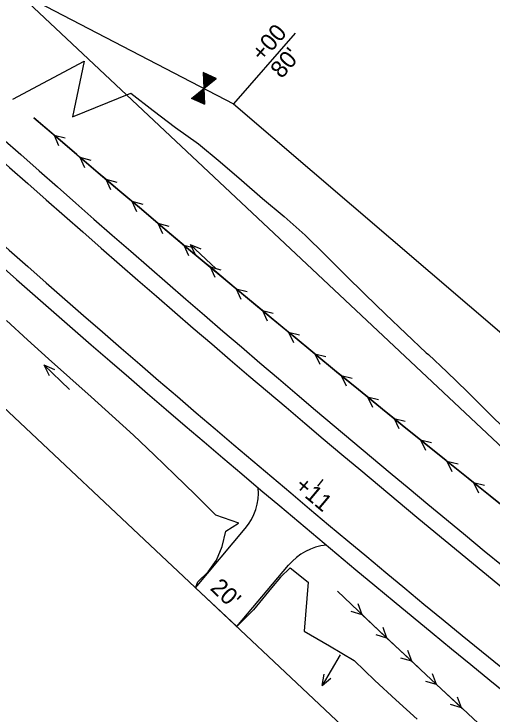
# Model space of a CAD drawing. Extents: x 1006695 to 1009377, y 1883329 to 1886115.
# Drawn here: x 1007248.3 to 1007416.8, y 1885056.9 to 1885303.6 of the extents above; entities that cross this region are included whole.
import ezdxf

# ---------------------------------------------------------------- set-up
doc = ezdxf.new("R2010")
doc.units = 0
for name, color, linetype in [('R_Drainage Ditch Lining', 7, 'Continuous'), ('R_Drive', 7, 'Continuous'), ('R_No Plot', 7, 'Continuous'), ('R_Prop Const Limits Cut', 7, 'Continuous'), ('R_Prop EOL', 7, 'Continuous'), ('R_Prop EOS', 7, 'Continuous'), ('R_ROW', 7, 'Continuous'), ('R_ROW Annot', 7, 'Continuous'), ('R_Water Annot', 7, 'Continuous'), ('S_EXIST_ROW', 7, 'Continuous')]:
    doc.layers.add(name, color=color, linetype=linetype)

msp = doc.modelspace()

# ---------------------------------------------------------------- linework, layer by layer
at = {"layer": 'R_Drainage Ditch Lining'}
for p, q in [((1007262.39, 1885260.93), (1007264.01, 1885257.28)), ((1007262.39, 1885260.93), (1007266.25, 1885259.91)), ((1007262.39, 1885260.93), (1007264.01, 1885257.28)), ((1007262.39, 1885260.93), (1007266.25, 1885259.91)), ((1007271.52, 1885253.14), (1007273.14, 1885249.49)), ((1007271.52, 1885253.14), (1007275.38, 1885252.12)), ((1007271.52, 1885253.14), (1007273.14, 1885249.49)), ((1007271.52, 1885253.14), (1007275.38, 1885252.12)), ((1007280.65, 1885245.36), (1007282.28, 1885241.71)), ((1007280.65, 1885245.36), (1007284.52, 1885244.35)), ((1007280.65, 1885245.36), (1007282.28, 1885241.71)), ((1007280.65, 1885245.36), (1007284.52, 1885244.35)), ((1007289.81, 1885237.6), (1007291.44, 1885233.95)), ((1007289.81, 1885237.6), (1007293.67, 1885236.59)), ((1007289.81, 1885237.6), (1007291.44, 1885233.95)), ((1007289.81, 1885237.6), (1007293.67, 1885236.59)), ((1007298.98, 1885229.86), (1007300.62, 1885226.22)), ((1007298.98, 1885229.86), (1007302.84, 1885228.86)), ((1007298.98, 1885229.86), (1007300.62, 1885226.22)), ((1007298.98, 1885229.86), (1007302.84, 1885228.86)), ((1007308.16, 1885222.14), (1007309.81, 1885218.5)), ((1007308.16, 1885222.14), (1007312.03, 1885221.15)), ((1007308.16, 1885222.14), (1007309.81, 1885218.5)), ((1007308.16, 1885222.14), (1007312.03, 1885221.15)), ((1007317.37, 1885214.44), (1007319.02, 1885210.8)), ((1007317.37, 1885214.44), (1007321.24, 1885213.46)), ((1007317.37, 1885214.44), (1007319.02, 1885210.8)), ((1007317.37, 1885214.44), (1007321.24, 1885213.46)), ((1007326.59, 1885206.75), (1007328.25, 1885203.12)), ((1007326.59, 1885206.75), (1007330.46, 1885205.78)), ((1007326.59, 1885206.75), (1007328.25, 1885203.12)), ((1007326.59, 1885206.75), (1007330.46, 1885205.78)), ((1007335.82, 1885199.09), (1007337.49, 1885195.46)), ((1007335.82, 1885199.09), (1007339.69, 1885198.13)), ((1007335.82, 1885199.09), (1007337.49, 1885195.46)), ((1007335.82, 1885199.09), (1007339.69, 1885198.13)), ((1007345.07, 1885191.45), (1007346.75, 1885187.82)), ((1007345.07, 1885191.45), (1007348.95, 1885190.49)), ((1007345.07, 1885191.45), (1007346.75, 1885187.82)), ((1007345.07, 1885191.45), (1007348.95, 1885190.49)), ((1007354.34, 1885183.82), (1007356.03, 1885180.2)), ((1007354.34, 1885183.82), (1007358.22, 1885182.88)), ((1007354.34, 1885183.82), (1007356.03, 1885180.2)), ((1007354.34, 1885183.82), (1007358.22, 1885182.88)), ((1007363.62, 1885176.22), (1007365.32, 1885172.6)), ((1007363.62, 1885176.22), (1007367.5, 1885175.28)), ((1007363.62, 1885176.22), (1007365.32, 1885172.6)), ((1007363.62, 1885176.22), (1007367.5, 1885175.28)), ((1007372.92, 1885168.63), (1007374.62, 1885165.02)), ((1007372.92, 1885168.63), (1007376.8, 1885167.7)), ((1007372.92, 1885168.63), (1007374.62, 1885165.02)), ((1007372.92, 1885168.63), (1007376.8, 1885167.7)), ((1007382.24, 1885161.07), (1007383.94, 1885157.46)), ((1007382.24, 1885161.07), (1007386.12, 1885160.14)), ((1007382.24, 1885161.07), (1007383.94, 1885157.46)), ((1007382.24, 1885161.07), (1007386.12, 1885160.14)), ((1007391.56, 1885153.52), (1007393.29, 1885149.92)), ((1007391.56, 1885153.52), (1007395.45, 1885152.61)), ((1007391.56, 1885153.52), (1007393.29, 1885149.92)), ((1007391.56, 1885153.52), (1007395.45, 1885152.61)), ((1007400.91, 1885146), (1007402.64, 1885142.39)), ((1007400.91, 1885146), (1007404.8, 1885145.09)), ((1007400.91, 1885146), (1007402.64, 1885142.39)), ((1007400.91, 1885146), (1007404.8, 1885145.09)), ((1007410.28, 1885138.49), (1007412.01, 1885134.89)), ((1007410.28, 1885138.49), (1007414.17, 1885137.59)), ((1007410.28, 1885138.49), (1007412.01, 1885134.89)), ((1007410.28, 1885138.49), (1007414.17, 1885137.59))]:
    msp.add_line(p, q, dxfattribs=at)
for points in [[(1007255.3, 1885267.02), (1007262.85, 1885260.54), (1007270.41, 1885254.08), (1007277.99, 1885247.62), (1007285.57, 1885241.19), (1007293.16, 1885234.76), (1007300.77, 1885228.35), (1007308.39, 1885221.95), (1007316.01, 1885215.56), (1007323.65, 1885209.19), (1007331.3, 1885202.83), (1007338.96, 1885196.49), (1007346.63, 1885190.16), (1007354.31, 1885183.84), (1007362.01, 1885177.54), (1007369.71, 1885171.25), (1007377.42, 1885164.97), (1007378.2, 1885164.34), (1007385.15, 1885158.71), (1007392.88, 1885152.46), (1007400.63, 1885146.22), (1007408.39, 1885140), (1007416.15, 1885133.79), (1007423.93, 1885127.6)], [(1007419.65, 1885131), (1007416.15, 1885133.79), (1007410.28, 1885138.49), (1007408.39, 1885140), (1007400.91, 1885146), (1007400.63, 1885146.22), (1007392.88, 1885152.46), (1007391.57, 1885153.52), (1007385.15, 1885158.71), (1007382.24, 1885161.07), (1007378.2, 1885164.34), (1007377.42, 1885164.97), (1007372.92, 1885168.63), (1007369.71, 1885171.25), (1007363.62, 1885176.22), (1007362.01, 1885177.54), (1007354.34, 1885183.82), (1007354.31, 1885183.84), (1007346.63, 1885190.16), (1007345.07, 1885191.45), (1007338.96, 1885196.49), (1007335.82, 1885199.09), (1007331.3, 1885202.83), (1007326.59, 1885206.75), (1007323.65, 1885209.19), (1007317.37, 1885214.44), (1007316.01, 1885215.56), (1007308.39, 1885221.95), (1007308.16, 1885222.14), (1007300.77, 1885228.35), (1007298.98, 1885229.86), (1007293.16, 1885234.76), (1007289.81, 1885237.6), (1007285.57, 1885241.19), (1007280.65, 1885245.36), (1007277.99, 1885247.62), (1007271.52, 1885253.14), (1007270.41, 1885254.08), (1007262.85, 1885260.54), (1007262.39, 1885260.94), (1007255.3, 1885267.02)]]:
    msp.add_lwpolyline(points, dxfattribs=at)
at = {"layer": 'R_Drive'}
for p, q in [((1007355.38, 1885137.19), (1007357.31, 1885139.49)), ((1007312.23, 1885101.38), (1007329.76, 1885122.25)), ((1007326.83, 1885087.67), (1007345.08, 1885109.38)), ((1007312.23, 1885101.38), (1007326.83, 1885087.67))]:
    msp.add_line(p, q, dxfattribs=at)
for centre, start, end in [((1007314.45, 1885135.12), 319.9599, 4.1596), ((1007360.39, 1885096.52), 95.7602, 139.9599)]:
    msp.add_arc(centre, 20, start, end, dxfattribs=at)
at = {"layer": 'R_No Plot'}
for p, q in [((1007371.01, 1885091.89), (1007369.63, 1885095.66)), ((1007371.01, 1885091.89), (1007367.16, 1885093.05)), ((1007379.75, 1885083.66), (1007378.36, 1885087.43)), ((1007379.75, 1885083.66), (1007375.89, 1885084.81)), ((1007388.5, 1885075.45), (1007387.1, 1885079.22)), ((1007388.5, 1885075.45), (1007384.64, 1885076.6)), ((1007397.27, 1885067.26), (1007395.86, 1885071.03)), ((1007397.27, 1885067.26), (1007393.41, 1885068.4)), ((1007406.05, 1885059.08), (1007404.64, 1885062.85)), ((1007406.05, 1885059.08), (1007402.19, 1885060.22))]:
    msp.add_line(p, q, dxfattribs=at)
for points in [[(1007362.3, 1885100.13), (1007369.61, 1885093.21), (1007376.94, 1885086.3), (1007384.27, 1885079.4), (1007391.63, 1885072.52), (1007398.99, 1885065.65), (1007406.37, 1885058.79), (1007413.76, 1885051.94), (1007421.16, 1885045.1), (1007428.58, 1885038.28), (1007436.01, 1885031.46), (1007443.45, 1885024.67), (1007450.9, 1885017.88), (1007458.37, 1885011.1), (1007465.85, 1885004.34), (1007473.34, 1884997.59), (1007480.85, 1884990.85), (1007488.37, 1884984.13), (1007495.9, 1884977.41), (1007503.44, 1884970.71), (1007510.99, 1884964.02)], [(1007362.3, 1885100.13), (1007369.61, 1885093.21), (1007371.01, 1885091.89), (1007376.94, 1885086.3), (1007379.75, 1885083.66), (1007384.27, 1885079.4), (1007388.5, 1885075.45), (1007391.63, 1885072.52), (1007397.27, 1885067.26), (1007398.99, 1885065.65), (1007406.05, 1885059.08), (1007406.37, 1885058.79), (1007413.76, 1885051.94)]]:
    msp.add_lwpolyline(points, dxfattribs=at)
at = {"layer": 'R_Prop Const Limits Cut'}
for points in [[(1007247.84, 1885273.6), (1007273.02, 1885286.94), (1007268.86, 1885267.33), (1007289.49, 1885275.67), (1007297.34, 1885269.61), (1007305.21, 1885263.58), (1007313.31, 1885257.81), (1007320.94, 1885251.51), (1007328.47, 1885245.09), (1007335.93, 1885238.6), (1007343.46, 1885232.18), (1007350.88, 1885225.64), (1007357.99, 1885218.73), (1007364.96, 1885211.65), (1007372.11, 1885204.79), (1007379.19, 1885197.83), (1007386.4, 1885191.04), (1007393.61, 1885184.22), (1007394.34, 1885183.55), (1007400.86, 1885177.46), (1007407.97, 1885170.53), (1007415.02, 1885163.52), (1007422.11, 1885156.56)], [(1007245.61, 1885195.62), (1007252.98, 1885188.78), (1007260.44, 1885182.04), (1007267.94, 1885175.34), (1007275.44, 1885168.64), (1007282.93, 1885161.94), (1007290.41, 1885155.21), (1007297.67, 1885148.23), (1007304.93, 1885141.24), (1007312.18, 1885134.25), (1007319.33, 1885127.13), (1007327.46, 1885124.25)], [(1007312.23, 1885101.38), (1007313.09, 1885103.5), (1007316.67, 1885107.03), (1007319.64, 1885111.06), (1007321.67, 1885115.89), (1007323, 1885121.3), (1007327.44, 1885124.1), (1007327.46, 1885124.25)], [(1007345.6, 1885108.44), (1007342.26, 1885105.12), (1007339, 1885101.32), (1007335.88, 1885097.42), (1007332.67, 1885093.58), (1007329.12, 1885090.04), (1007326.83, 1885087.67)], [(1007345.6, 1885108.44), (1007351.92, 1885103.38), (1007350.58, 1885086.04), (1007359.46, 1885080.96), (1007368.2, 1885075.72), (1007375.44, 1885068.67), (1007382.9, 1885061.88), (1007390.37, 1885055.09)]]:
    msp.add_lwpolyline(points, dxfattribs=at)
at = {"layer": 'R_Prop EOL'}
for radius, start, end in [(5718.58, 226.84988, 232.3673), (5740.58, 226.849882, 232.431241)]:
    msp.add_arc((1011043.29, 1889526.02), radius, start, end, dxfattribs=at)
at = {"layer": 'R_Prop EOS'}
for radius, start, end in [(5712.58, 226.84988, 232.3673), (5746.58, 226.849882, 232.431241)]:
    msp.add_arc((1011043.29, 1889526.02), radius, start, end, dxfattribs=at)
at = {"layer": 'R_ROW'}
for p, q in [((1007248.69, 1885311.97), (1007325.67, 1885271.96)), ((1007315, 1885282.95), (1007319.55, 1885280.91)), ((1007315, 1885282.84), (1007319.46, 1885280.84)), ((1007315.01, 1885282.73), (1007319.37, 1885280.77)), ((1007315.01, 1885282.62), (1007319.29, 1885280.7)), ((1007315.02, 1885282.51), (1007319.2, 1885280.63)), ((1007315.02, 1885282.39), (1007319.11, 1885280.56)), ((1007315.02, 1885282.28), (1007319.03, 1885280.49)), ((1007315.03, 1885282.17), (1007318.94, 1885280.42)), ((1007315.03, 1885282.06), (1007318.85, 1885280.35)), ((1007315.04, 1885281.95), (1007318.77, 1885280.28)), ((1007315.04, 1885281.83), (1007318.68, 1885280.2)), ((1007315.05, 1885281.72), (1007318.59, 1885280.13)), ((1007315.05, 1885281.61), (1007318.51, 1885280.06)), ((1007315.06, 1885281.5), (1007318.42, 1885279.99)), ((1007315.06, 1885281.39), (1007318.33, 1885279.92)), ((1007315.07, 1885281.28), (1007318.25, 1885279.85)), ((1007315.07, 1885281.16), (1007318.16, 1885279.78)), ((1007315.08, 1885281.05), (1007318.08, 1885279.71)), ((1007315.08, 1885280.94), (1007317.99, 1885279.64)), ((1007315.09, 1885280.83), (1007317.9, 1885279.57)), ((1007315.09, 1885280.72), (1007317.82, 1885279.5)), ((1007315.1, 1885280.61), (1007317.73, 1885279.43)), ((1007315.1, 1885280.49), (1007317.64, 1885279.35)), ((1007315.11, 1885280.38), (1007317.56, 1885279.28)), ((1007315.11, 1885280.27), (1007317.47, 1885279.21)), ((1007315.11, 1885280.16), (1007317.38, 1885279.14)), ((1007315.12, 1885280.05), (1007317.3, 1885279.07)), ((1007315.12, 1885279.94), (1007317.21, 1885279)), ((1007315.13, 1885279.82), (1007317.12, 1885278.93)), ((1007315.13, 1885279.71), (1007317.04, 1885278.86)), ((1007315.03, 1885277.22), (1007315.24, 1885277.13)), ((1007315.12, 1885277.29), (1007315.24, 1885277.24)), ((1007315.14, 1885279.6), (1007316.95, 1885278.79)), ((1007315.14, 1885279.49), (1007316.86, 1885278.72)), ((1007315.15, 1885279.38), (1007316.78, 1885278.65)), ((1007315.15, 1885279.27), (1007316.69, 1885278.58)), ((1007315.16, 1885279.15), (1007316.6, 1885278.51)), ((1007315.16, 1885279.04), (1007316.52, 1885278.43)), ((1007315.17, 1885278.93), (1007316.43, 1885278.36)), ((1007315.17, 1885278.82), (1007316.34, 1885278.29)), ((1007315.18, 1885278.71), (1007316.26, 1885278.22)), ((1007315.18, 1885278.6), (1007316.17, 1885278.15)), ((1007315.19, 1885278.48), (1007316.08, 1885278.08)), ((1007315.19, 1885278.37), (1007316, 1885278.01)), ((1007315.19, 1885278.26), (1007315.91, 1885277.94)), ((1007315.2, 1885278.15), (1007315.83, 1885277.87)), ((1007315.2, 1885278.04), (1007315.74, 1885277.8)), ((1007315.21, 1885277.93), (1007315.65, 1885277.73)), ((1007315.21, 1885277.81), (1007315.57, 1885277.66)), ((1007315.21, 1885277.36), (1007315.23, 1885277.35)), ((1007315.22, 1885277.7), (1007315.48, 1885277.58)), ((1007315.22, 1885277.59), (1007315.39, 1885277.51)), ((1007315.23, 1885277.48), (1007315.31, 1885277.44)), ((1007312.01, 1885274.74), (1007315.41, 1885273.22)), ((1007312.09, 1885274.81), (1007315.4, 1885273.33)), ((1007312.18, 1885274.88), (1007315.4, 1885273.44)), ((1007312.27, 1885274.96), (1007315.39, 1885273.55)), ((1007312.35, 1885275.03), (1007315.39, 1885273.66)), ((1007312.44, 1885275.1), (1007315.38, 1885273.78)), ((1007312.52, 1885275.17), (1007315.38, 1885273.89)), ((1007312.61, 1885275.24), (1007315.37, 1885274)), ((1007312.7, 1885275.31), (1007315.37, 1885274.11)), ((1007312.78, 1885275.38), (1007315.37, 1885274.22)), ((1007312.87, 1885275.45), (1007315.36, 1885274.33)), ((1007312.96, 1885275.52), (1007315.36, 1885274.45)), ((1007313.04, 1885275.59), (1007315.35, 1885274.56)), ((1007313.13, 1885275.66), (1007315.35, 1885274.67)), ((1007313.22, 1885275.73), (1007315.34, 1885274.78)), ((1007313.3, 1885275.8), (1007315.34, 1885274.89)), ((1007313.39, 1885275.88), (1007315.33, 1885275)), ((1007313.48, 1885275.95), (1007315.33, 1885275.12)), ((1007313.56, 1885276.02), (1007315.32, 1885275.23)), ((1007313.65, 1885276.09), (1007315.32, 1885275.34)), ((1007313.74, 1885276.16), (1007315.31, 1885275.45)), ((1007313.82, 1885276.23), (1007315.31, 1885275.56)), ((1007313.91, 1885276.3), (1007315.3, 1885275.67)), ((1007314, 1885276.37), (1007315.3, 1885275.79)), ((1007314.08, 1885276.44), (1007315.29, 1885275.9)), ((1007314.17, 1885276.51), (1007315.29, 1885276.01)), ((1007314.26, 1885276.58), (1007315.29, 1885276.12)), ((1007314.34, 1885276.65), (1007315.28, 1885276.23)), ((1007314.43, 1885276.72), (1007315.28, 1885276.35)), ((1007314.51, 1885276.8), (1007315.27, 1885276.46)), ((1007314.6, 1885276.87), (1007315.27, 1885276.57)), ((1007314.69, 1885276.94), (1007315.26, 1885276.68)), ((1007314.77, 1885277.01), (1007315.26, 1885276.79)), ((1007314.86, 1885277.08), (1007315.25, 1885276.9)), ((1007314.95, 1885277.15), (1007315.25, 1885277.02)), ((1007310.97, 1885273.89), (1007315.46, 1885271.88)), ((1007311.05, 1885273.96), (1007315.46, 1885271.99)), ((1007311.14, 1885274.03), (1007315.45, 1885272.1)), ((1007311.23, 1885274.11), (1007315.45, 1885272.21)), ((1007311.31, 1885274.18), (1007315.45, 1885272.32)), ((1007311.4, 1885274.25), (1007315.44, 1885272.44)), ((1007311.49, 1885274.32), (1007315.44, 1885272.55)), ((1007311.57, 1885274.39), (1007315.43, 1885272.66)), ((1007311.66, 1885274.46), (1007315.43, 1885272.77)), ((1007311.75, 1885274.53), (1007315.42, 1885272.88)), ((1007311.83, 1885274.6), (1007315.42, 1885272.99)), ((1007311.92, 1885274.67), (1007315.41, 1885273.11)), ((1007325.67, 1885271.96), (1007626.33, 1885014.27))]:
    msp.add_line(p, q, dxfattribs=at)
for points in [[(1007315, 1885282.97), (1007315.23, 1885277.38), (1007319.56, 1885280.92)], [(1007310.9, 1885273.84), (1007315.23, 1885277.38), (1007315.47, 1885271.8)]]:
    msp.add_lwpolyline(points, close=True, dxfattribs=at)
at = {"layer": 'R_ROW Annot'}
msp.add_line((1007347.39, 1885296.81), (1007325.67, 1885271.96), dxfattribs=at)
at = {"layer": 'R_Water Annot'}
for p, q in [((1007319.56, 1885213.8), (1007310.4, 1885222.41)), ((1007310.4, 1885222.41), (1007314.17, 1885220.8)), ((1007310.4, 1885222.41), (1007312.25, 1885218.75)), ((1007267.89, 1885171.22), (1007258.81, 1885179.92)), ((1007258.81, 1885179.92), (1007262.56, 1885178.27)), ((1007258.81, 1885179.92), (1007260.62, 1885176.24)), ((1007363.21, 1885077.76), (1007356.85, 1885066.92)), ((1007356.85, 1885066.92), (1007357.59, 1885070.94)), ((1007356.85, 1885066.92), (1007360.01, 1885069.53))]:
    msp.add_line(p, q, dxfattribs=at)
at = {"layer": 'S_EXIST_ROW'}
for p, q in [((1007540.25, 1885038.12), (1007248.69, 1885311.97)), ((1007392.06, 1885026.41), (1007173.38, 1885231.79))]:
    msp.add_line(p, q, dxfattribs=at)

# ---------------------------------------------------------------- texts
at = {"layer": 'R_Drive'}
for s, rotation, p in [('+11', 319.9599, (1007346.8, 1885136.57)), ("20'", 316.795, (1007317.12, 1885100.91))]:
    msp.add_text(s, height=6, rotation=rotation, dxfattribs=at).set_placement(p)
at = {"layer": 'R_ROW Annot'}
for s, p in [('+00', (1007335.84, 1885286.48)), ("80'", (1007342.62, 1885280.56))]:
    msp.add_text(s, height=6, rotation=48.8499, dxfattribs=at).set_placement(p)

doc.saveas('drawing.dxf')
